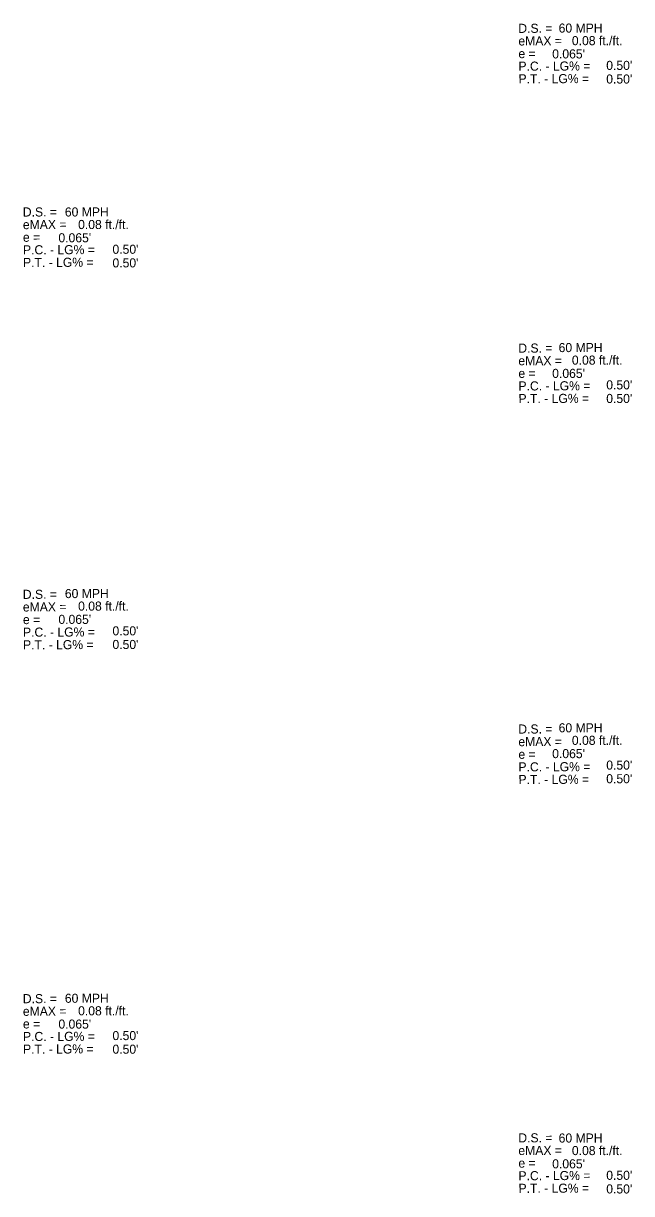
# Model space of a CAD drawing. Extents: x 1609513 to 1612809, y 1095191 to 1097244.
# Drawn here: x 1612407 to 1612809, y 1095291 to 1096062 of the extents above; entities that cross this region are included whole.
import ezdxf

# ---------------------------------------------------------------- set-up
doc = ezdxf.new("R2010")
doc.units = 0
doc.layers.add('RD_HC_Data_50', color=7, linetype='Continuous')

msp = doc.modelspace()

# ---------------------------------------------------------------- texts
at = {"layer": 'RD_HC_Data_50'}
for s, p in [('D.S. = ', (1612734.01, 1096056.14)), ('eMAX = ', (1612734.04, 1096047.82)), ('e = ', (1612734.08, 1096039.5)), ('P.C. - LG% = ', (1612734.11, 1096031.18)), ('P.T. - LG% = ', (1612734.14, 1096022.86)), ('D.S. = ', (1612406.88, 1095935.02)), ('eMAX = ', (1612406.91, 1095926.7)), ('e = ', (1612406.94, 1095918.38)), ('P.C. - LG% = ', (1612406.98, 1095910.06)), ('P.T. - LG% = ', (1612407.01, 1095901.74)), ('D.S. = ', (1612734.01, 1095845.23)), ('eMAX = ', (1612734.04, 1095836.91)), ('e = ', (1612734.08, 1095828.59)), ('P.C. - LG% = ', (1612734.11, 1095820.27)), ('P.T. - LG% = ', (1612734.14, 1095811.95)), ('D.S. = ', (1612406.88, 1095682.84)), ('eMAX = ', (1612406.91, 1095674.52)), ('e = ', (1612406.94, 1095666.2)), ('P.C. - LG% = ', (1612406.98, 1095657.88)), ('P.T. - LG% = ', (1612407.01, 1095649.56)), ('D.S. = ', (1612734.01, 1095594)), ('eMAX = ', (1612734.04, 1095585.68)), ('e = ', (1612734.08, 1095577.36)), ('P.C. - LG% = ', (1612734.11, 1095569.04)), ('P.T. - LG% = ', (1612734.14, 1095560.72)), ('D.S. = ', (1612406.88, 1095416.16)), ('eMAX = ', (1612406.91, 1095407.84)), ('e = ', (1612406.94, 1095399.52)), ('P.C. - LG% = ', (1612406.98, 1095391.2)), ('P.T. - LG% = ', (1612407.01, 1095382.88)), ('D.S. = ', (1612734.01, 1095324.35)), ('eMAX = ', (1612734.04, 1095316.03)), ('e = ', (1612734.08, 1095307.71)), ('P.C. - LG% = ', (1612734.11, 1095299.39)), ('P.T. - LG% = ', (1612734.14, 1095291.07))]:
    msp.add_text(s, height=6, rotation=0.2225, dxfattribs=at).set_placement(p)
for s, p in [('60 MPH', (1612760.62, 1096056.32)), ('0.08 ft./ft.', (1612769.37, 1096048.04)), ("0.065'", (1612756.37, 1096039.29)), ("0.50'", (1612792.06, 1096031.72)), ("0.50'", (1612792.06, 1096022.74)), ('60 MPH', (1612434.62, 1095935.05)), ('0.08 ft./ft.', (1612443.37, 1095926.77)), ("0.065'", (1612430.37, 1095918.02)), ("0.50'", (1612466.06, 1095910.45)), ("0.50'", (1612466.06, 1095901.47)), ('60 MPH', (1612760.62, 1095845.61)), ('0.08 ft./ft.', (1612769.37, 1095837.33)), ("0.065'", (1612756.37, 1095828.58)), ("0.50'", (1612792.06, 1095821.01)), ("0.50'", (1612792.06, 1095812.03)), ('60 MPH', (1612434.62, 1095683.37)), ('0.08 ft./ft.', (1612443.37, 1095675.09)), ("0.065'", (1612430.37, 1095666.34)), ("0.50'", (1612466.06, 1095658.77)), ("0.50'", (1612466.06, 1095649.78)), ('60 MPH', (1612760.62, 1095594.82)), ('0.08 ft./ft.', (1612769.37, 1095586.55)), ("0.065'", (1612756.37, 1095577.8)), ("0.50'", (1612792.06, 1095570.23)), ("0.50'", (1612792.06, 1095561.24)), ('60 MPH', (1612434.62, 1095416.44)), ('0.08 ft./ft.', (1612443.37, 1095408.16)), ("0.065'", (1612430.37, 1095399.41)), ("0.50'", (1612466.06, 1095391.84)), ("0.50'", (1612466.06, 1095382.85)), ('60 MPH', (1612760.62, 1095324.27)), ('0.08 ft./ft.', (1612769.37, 1095316)), ("0.065'", (1612756.37, 1095307.25)), ("0.50'", (1612792.06, 1095299.68)), ("0.50'", (1612792.06, 1095290.69))]:
    msp.add_text(s, height=6, dxfattribs=at).set_placement(p)

doc.saveas('drawing.dxf')
